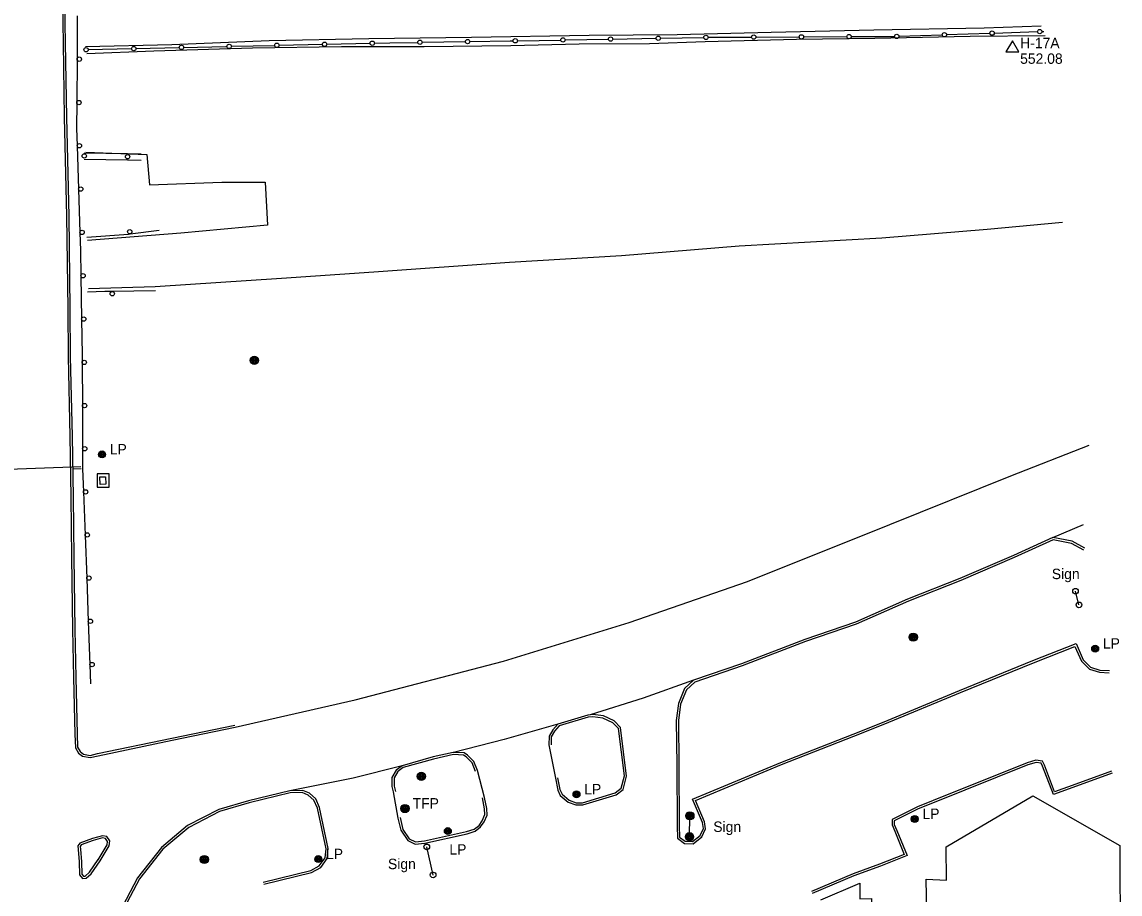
# Model space of a CAD drawing. Extents: x 2402803 to 2427059, y 6985292 to 6997652.
# Drawn here: x 2426548 to 2427055, y 6991142 to 6991544 of the extents above; entities that cross this region are included whole.
import ezdxf

# ---------------------------------------------------------------- set-up
doc = ezdxf.new("R2010")
doc.units = 0
for name, color, linetype in [('p_control ground ctrl', 7, 'Continuous'), ('p_dtm sidewalk', 7, 'Continuous'), ('p_road - paved curb', 7, 'Continuous'), ('p_road bridge end', 7, 'Continuous'), ('p_road conc barrier', 7, 'Continuous'), ('p_road guard fences', 7, 'Continuous'), ('p_road guard rails', 7, 'Continuous'), ('p_structure building', 7, 'Continuous'), ('p_structure general', 7, 'Continuous'), ('p_structure sidewalk', 7, 'Continuous'), ('p_structure sign', 7, 'Continuous'), ('p_structure slab', 7, 'Continuous'), ('p_utility manhole', 7, 'Continuous'), ('V7 LEVEL 31', 7, 'Continuous')]:
    doc.layers.add(name, color=color, linetype=linetype)

msp = doc.modelspace()

# ---------------------------------------------------------------- linework, layer by layer
at = {"layer": 'p_control ground ctrl'}
for p, q in [((2427005.25, 6991535.28), (2427002.25, 6991530.08)), ((2427008.25, 6991530.08), (2427005.25, 6991535.28)), ((2427005.25, 6991531.8), (2427005.25, 6991531.84)), ((2427002.25, 6991530.08), (2427008.25, 6991530.08))]:
    msp.add_line(p, q, dxfattribs=at)
at = {"layer": 'p_dtm sidewalk'}
msp.add_lwpolyline([(2426916.9, 6991138.89), (2426934.89, 6991146.51), (2426934.84, 6991139.28), (2426940.18, 6991139.42), (2426940.6, 6991129.38), (2426935.26, 6991129.19), (2426935.19, 6991127.67), (2426919.78, 6991132.5)], dxfattribs=at)
at = {"layer": 'p_road - paved curb'}
for points in [[(2426566.6, 6991580.37), (2426567.31, 6991534.06), (2426567.84, 6991500.02), (2426568.98, 6991454.31), (2426569.5, 6991411.55), (2426569.68, 6991389.4), (2426570.46, 6991352.79), (2426570.97, 6991324.68), (2426571.26, 6991296.91), (2426571.72, 6991263.57), (2426572.15, 6991241.38), (2426572.83, 6991215.32), (2426573.01, 6991209), (2426574.47, 6991206.56), (2426576.29, 6991205.17), (2426579.88, 6991204.48), (2426583.46, 6991205.37), (2426617.71, 6991212.47), (2426646.78, 6991218.51)], [(2426567.6, 6991580.39), (2426568.31, 6991534.08), (2426568.84, 6991500.04), (2426569.98, 6991454.33), (2426570.5, 6991411.56), (2426570.68, 6991389.41), (2426571.46, 6991352.81), (2426571.97, 6991324.69), (2426572.26, 6991296.92), (2426572.72, 6991263.59), (2426573.15, 6991241.4), (2426573.83, 6991215.35), (2426574, 6991209.29), (2426575.23, 6991207.24), (2426576.71, 6991206.11), (2426579.85, 6991205.5), (2426583.24, 6991206.35), (2426617.51, 6991213.45), (2426646.58, 6991219.49)], [(2426577.74, 6991532.56), (2426617.52, 6991533.57), (2426662.45, 6991535.42), (2426708.44, 6991536.29), (2426755.67, 6991536.93), (2426810.09, 6991537.76), (2426850.57, 6991538.13), (2426894.03, 6991539.26), (2426941.38, 6991540.29), (2426992.17, 6991541.15), (2427018.52, 6991542.07)], [(2427020.3, 6991537.5), (2426985.78, 6991537.17), (2426941.84, 6991536.32), (2426905.63, 6991535.84), (2426863.6, 6991534.7), (2426837.82, 6991533.85), (2426805.41, 6991533.7), (2426773.87, 6991532.91), (2426733.9, 6991532.48), (2426695.7, 6991532.41), (2426654.67, 6991531.77), (2426609.25, 6991530.45), (2426578.35, 6991529.16)], [(2426577.8, 6991483.77), (2426605.92, 6991482.82), (2426607.15, 6991468.72), (2426640.55, 6991469.94), (2426660.51, 6991470), (2426661.56, 6991450.15), (2426621.64, 6991446.53), (2426578.57, 6991443.15)], [(2426579, 6991420.97), (2426609.85, 6991421.93), (2426668.15, 6991425.68), (2426710.71, 6991428.7), (2426773.29, 6991433.03), (2426824.9, 6991436.1), (2426879.22, 6991440.63), (2426944.98, 6991444.33), (2426993.56, 6991448.33), (2427028.38, 6991451.56)], [(2426646.78, 6991218.51), (2426702.07, 6991231.21), (2426770.51, 6991248.95), (2426828.52, 6991266.8), (2426883.11, 6991285.77), (2426948.69, 6991312.02), (2427004.55, 6991334.44), (2427040.69, 6991348.63)], [(2427023.92, 6991306.03), (2427038.04, 6991312.12)], [(2427038.63, 6991301.15), (2427032.81, 6991304.28), (2427023.92, 6991306.03), (2427005.68, 6991297.8), (2426981.02, 6991287.2), (2426956.89, 6991277.57), (2426932.82, 6991266.94), (2426909.49, 6991258.93), (2426880.31, 6991247.83), (2426858.19, 6991240.23), (2426854.02, 6991236.37), (2426851.16, 6991229.48), (2426850.15, 6991221.62), (2426850.4, 6991201.02), (2426850.58, 6991172.94), (2426850.74, 6991167.34), (2426853.95, 6991164.89), (2426858.02, 6991164.73), (2426861.99, 6991167.95), (2426863.72, 6991171.61), (2426863.19, 6991174.8), (2426859.02, 6991184.76), (2426898.75, 6991201.34), (2426932.12, 6991214.44), (2426946.45, 6991220.08), (2426981.27, 6991234.6), (2427015.01, 6991248.29), (2427034.09, 6991255.81), (2427037.09, 6991249.03), (2427040.78, 6991245.34), (2427045.43, 6991243.91), (2427049.95, 6991243.66)], [(2427038.16, 6991300.27), (2427032.47, 6991303.33), (2427024.04, 6991304.99), (2427006.08, 6991296.88), (2426981.4, 6991286.28), (2426957.28, 6991276.65), (2426933.19, 6991266.01), (2426909.83, 6991257.99), (2426880.65, 6991246.89), (2426858.71, 6991239.35), (2426854.86, 6991235.78), (2426852.13, 6991229.22), (2426851.15, 6991221.56), (2426851.4, 6991201.03), (2426851.58, 6991172.96), (2426851.73, 6991167.85), (2426854.31, 6991165.88), (2426857.68, 6991165.74), (2426861.18, 6991168.58), (2426862.68, 6991171.75), (2426862.22, 6991174.52), (2426857.71, 6991185.3), (2426898.37, 6991202.27), (2426931.75, 6991215.37), (2426946.07, 6991221.01), (2426980.89, 6991235.52), (2427014.64, 6991249.22), (2427034.62, 6991257.09), (2427037.93, 6991249.61), (2427041.31, 6991246.22), (2427045.61, 6991244.9), (2427050.01, 6991244.66)], [(2426858.19, 6991240.23), (2426834.88, 6991231.88), (2426810.51, 6991224.21)], [(2426794.49, 6991195.05), (2426795.52, 6991189.47), (2426796.71, 6991186.98), (2426800.35, 6991183.97), (2426803.8, 6991182.63), (2426807.11, 6991182.66), (2426822.43, 6991187.3), (2426825.66, 6991189.73), (2426827.3, 6991195.98), (2426824.48, 6991218.36), (2426821.56, 6991221.43), (2426816.55, 6991223.7), (2426811.7, 6991224.37), (2426809.33, 6991224.06), (2426795.57, 6991219.97), (2426793.21, 6991217.27), (2426791.49, 6991214.39), (2426791.48, 6991210.34)], [(2426795.47, 6991195.23), (2426796.48, 6991189.78), (2426797.52, 6991187.61), (2426800.86, 6991184.84), (2426803.98, 6991183.63), (2426806.96, 6991183.66), (2426821.97, 6991188.21), (2426824.78, 6991190.32), (2426826.28, 6991196.05), (2426823.53, 6991217.91), (2426820.97, 6991220.6), (2426816.27, 6991222.73), (2426811.7, 6991223.36), (2426809.54, 6991223.08), (2426796.13, 6991219.09), (2426794.02, 6991216.68), (2426792.49, 6991214.11), (2426792.48, 6991210.34)], [(2426795.57, 6991219.97), (2426770.79, 6991212.79), (2426747.41, 6991206.89)], [(2426758.52, 6991198.53), (2426756.82, 6991202.65), (2426753.88, 6991205.69), (2426752.35, 6991206.64), (2426747.33, 6991206.89), (2426737.98, 6991204.79), (2426723.77, 6991200.76), (2426720.97, 6991198.74), (2426719.05, 6991195.36), (2426719.03, 6991191.2), (2426719.65, 6991188.63)], [(2426791.48, 6991210.34), (2426794.49, 6991195.05)], [(2426757.6, 6991198.15), (2426755.97, 6991202.09), (2426753.25, 6991204.91), (2426752.04, 6991205.65), (2426747.42, 6991205.88), (2426738.23, 6991203.82), (2426724.21, 6991199.85), (2426721.73, 6991198.06), (2426720.05, 6991195.09), (2426720.03, 6991191.32), (2426720.62, 6991188.86)], [(2427050.95, 6991198.31), (2427034.52, 6991192.25), (2427024.73, 6991188.73), (2427020.11, 6991200.95), (2427019.1, 6991202.88), (2427016.09, 6991203.27), (2427012, 6991202.11), (2426968.73, 6991184.73), (2426961.42, 6991181.77), (2426949.74, 6991175.97), (2426949.75, 6991173.49), (2426950.98, 6991170.5), (2426955.36, 6991159.83), (2426944.01, 6991155.37), (2426931.79, 6991150.92), (2426912.53, 6991142.7)], [(2427051.3, 6991197.37), (2427034.86, 6991191.31), (2427024.14, 6991187.46), (2427019.2, 6991200.54), (2427018.46, 6991201.96), (2427016.17, 6991202.25), (2427012.32, 6991201.16), (2426969.1, 6991183.8), (2426961.83, 6991180.86), (2426950.74, 6991175.35), (2426950.75, 6991173.69), (2426951.9, 6991170.88), (2426956.67, 6991159.27), (2426944.36, 6991154.43), (2426932.16, 6991149.99), (2426912.92, 6991141.78)], [(2426723.77, 6991200.76), (2426701.11, 6991194.96), (2426671.9, 6991189.21)], [(2426761.79, 6991186.15), (2426758.52, 6991198.53)], [(2426659.91, 6991146.05), (2426681.98, 6991151.49), (2426686.16, 6991153.8), (2426689.22, 6991157.9), (2426689.69, 6991162.48), (2426685.62, 6991181.44), (2426683.89, 6991185.45), (2426681, 6991188.04), (2426677.89, 6991189.34), (2426671.9, 6991189.21), (2426652.89, 6991184.53), (2426639.18, 6991180.59), (2426624.76, 6991173.13), (2426612.68, 6991162.95), (2426601.73, 6991149.07), (2426592.98, 6991132.61)], [(2426659.67, 6991147.02), (2426681.61, 6991152.43), (2426685.49, 6991154.57), (2426688.25, 6991158.28), (2426688.68, 6991162.42), (2426684.66, 6991181.13), (2426683.06, 6991184.85), (2426680.46, 6991187.18), (2426677.7, 6991188.34), (2426672.03, 6991188.21), (2426653.15, 6991183.56), (2426639.55, 6991179.66), (2426625.32, 6991172.29), (2426613.4, 6991162.25), (2426602.57, 6991148.52), (2426593.9, 6991132.22)], [(2426719.65, 6991188.63), (2426721.8, 6991176.55)], [(2426721.8, 6991176.55), (2426723.11, 6991170.94), (2426726.33, 6991166.3), (2426729.71, 6991164.6), (2426734.24, 6991165.09), (2426753.68, 6991169.38), (2426757.37, 6991170.55), (2426759.95, 6991172.54), (2426761.52, 6991174.8), (2426762.96, 6991177.99), (2426762.77, 6991180.97), (2426761.79, 6991186.15)], [(2426722.77, 6991176.78), (2426724.04, 6991171.35), (2426727.01, 6991167.08), (2426729.9, 6991165.63), (2426734.08, 6991166.08), (2426753.42, 6991170.35), (2426756.9, 6991171.45), (2426759.22, 6991173.24), (2426760.65, 6991175.3), (2426761.95, 6991178.17), (2426761.78, 6991180.84), (2426760.81, 6991185.96)], [(2426580.96, 6991167.16), (2426575.09, 6991165.08), (2426574.2, 6991163.8), (2426574.32, 6991162.14), (2426574.79, 6991156.41), (2426574.93, 6991150.41), (2426576.26, 6991148.74), (2426577.95, 6991148.89), (2426580.27, 6991150.91), (2426584.41, 6991156.85)], [(2426581.29, 6991166.22), (2426575.73, 6991164.24), (2426575.22, 6991163.52), (2426575.32, 6991162.22), (2426575.79, 6991156.46), (2426575.92, 6991150.77), (2426576.71, 6991149.78), (2426577.54, 6991149.86), (2426579.52, 6991151.58), (2426583.59, 6991157.42)], [(2426584.38, 6991156.85), (2426588.62, 6991163.84), (2426588.9, 6991166.09), (2426587.55, 6991168.04), (2426585.55, 6991168.43), (2426580.96, 6991167.16)], [(2426583.52, 6991157.37), (2426587.65, 6991164.18), (2426587.86, 6991165.83), (2426586.96, 6991167.14), (2426585.59, 6991167.4), (2426581.23, 6991166.2)]]:
    msp.add_lwpolyline(points, dxfattribs=at)
at = {"layer": 'p_road bridge end'}
msp.add_lwpolyline([(2426485.53, 6991336.63), (2426533.57, 6991337.32), (2426575.5, 6991338.77)], dxfattribs=at)
at = {"layer": 'p_road conc barrier'}
for p, q in [((2426577.05, 6991480.58), (2426597.05, 6991480.23)), ((2426577.1, 6991483.58), (2426597.1, 6991483.23)), ((2426597.05, 6991480.23), (2426603.36, 6991480.12)), ((2426597.1, 6991483.23), (2426603.41, 6991483.12))]:
    msp.add_line(p, q, dxfattribs=at)
for centre in [(2426577.08, 6991482.08), (2426597.07, 6991481.73)]:
    msp.add_circle(centre, 1, dxfattribs=at)
at = {"layer": 'p_road guard fences'}
for p, q in [((2426776.91, 6991535.23), (2426796.91, 6991535.59)), ((2426798.91, 6991535.63), (2426818.91, 6991535.99)), ((2426820.91, 6991536.03), (2426840.9, 6991536.39)), ((2426842.9, 6991536.43), (2426862.9, 6991536.79)), ((2426886.9, 6991536.95), (2426906.9, 6991537.05)), ((2426908.9, 6991537.06), (2426928.9, 6991537.16)), ((2426930.9, 6991537.17), (2426950.89, 6991537.27)), ((2426952.89, 6991537.33), (2426972.88, 6991538)), ((2426974.88, 6991538.06), (2426994.87, 6991538.73)), ((2426996.87, 6991538.8), (2427016.86, 6991539.46)), ((2427018.86, 6991539.53), (2427019.81, 6991539.56)), ((2426578.97, 6991531.16), (2426598.96, 6991531.62)), ((2426600.96, 6991531.66), (2426620.96, 6991532.12)), ((2426644.95, 6991532.68), (2426664.95, 6991533.12)), ((2426666.94, 6991533.17), (2426686.94, 6991533.61)), ((2426688.94, 6991533.66), (2426708.93, 6991534.11)), ((2426732.92, 6991534.54), (2426752.92, 6991534.85))]:
    msp.add_line(p, q, dxfattribs=at)
for points in [[(2426754.92, 6991534.88), (2426773.6, 6991535.17), (2426774.91, 6991535.19)], [(2426864.9, 6991536.83), (2426865.5, 6991536.84), (2426884.9, 6991536.94)], [(2426622.96, 6991532.17), (2426642.48, 6991532.62), (2426642.95, 6991532.63)], [(2426710.93, 6991534.15), (2426718.1, 6991534.31), (2426730.92, 6991534.51)]]:
    msp.add_lwpolyline(points, dxfattribs=at)
for centre in [(2427017.86, 6991539.49), (2426731.92, 6991534.52), (2426753.92, 6991534.87), (2426775.91, 6991535.21), (2426797.91, 6991535.61), (2426819.91, 6991536.01), (2426841.9, 6991536.41), (2426863.9, 6991536.81), (2426885.9, 6991536.94), (2426907.9, 6991537.05), (2426929.9, 6991537.16), (2426951.89, 6991537.27), (2426973.88, 6991538.03), (2426995.87, 6991538.76), (2426577.97, 6991531.13), (2426599.96, 6991531.64), (2426621.96, 6991532.15), (2426643.95, 6991532.65), (2426665.94, 6991533.14), (2426687.94, 6991533.64), (2426709.93, 6991534.13)]:
    msp.add_circle(centre, 1, dxfattribs=at)
at = {"layer": 'p_road guard rails'}
for p, q in [((2426573.78, 6991526.75), (2426573.67, 6991506.75)), ((2426573.86, 6991486.76), (2426574.5, 6991466.77)), ((2426574.5, 6991466.77), (2426575.13, 6991446.78)), ((2426598.22, 6991446.12), (2426611.68, 6991447.85)), ((2426575.57, 6991426.8), (2426575.87, 6991406.83)), ((2426610, 6991419.81), (2426590.01, 6991419.53)), ((2426576.13, 6991386.86), (2426576.22, 6991366.92)), ((2426576.22, 6991366.92), (2426576.3, 6991346.98)), ((2426576.74, 6991327.07), (2426577.48, 6991307.18)), ((2426578.22, 6991287.26), (2426578.97, 6991267.34)), ((2426578.97, 6991267.34), (2426579.71, 6991247.41)), ((2426579.71, 6991247.41), (2426580.04, 6991238.54))]:
    msp.add_line(p, q, dxfattribs=at)
for points in [[(2426573.84, 6991546.75), (2426573.88, 6991544.47), (2426573.78, 6991526.75)], [(2426573.67, 6991506.75), (2426573.6, 6991494.86), (2426573.86, 6991486.76)], [(2426575.13, 6991446.78), (2426575.4, 6991438.4), (2426575.57, 6991426.8)], [(2426578.28, 6991444.61), (2426597.49, 6991446.03), (2426598.22, 6991446.12)], [(2426590.01, 6991419.53), (2426586.61, 6991419.48), (2426578.6, 6991419.23)], [(2426575.87, 6991406.83), (2426576.12, 6991390.27), (2426576.13, 6991386.86)], [(2426576.3, 6991346.98), (2426576.34, 6991337.68), (2426576.74, 6991327.07)], [(2426577.48, 6991307.18), (2426577.49, 6991306.98), (2426578.22, 6991287.26)]]:
    msp.add_lwpolyline(points, dxfattribs=at)
for centre in [(2426574.78, 6991526.75), (2426574.67, 6991506.75), (2426574.86, 6991486.79), (2426575.5, 6991466.8), (2426576.13, 6991446.81), (2426598.09, 6991447.12), (2426576.57, 6991426.81), (2426590.02, 6991418.53), (2426576.87, 6991406.84), (2426577.13, 6991386.86), (2426577.22, 6991366.93), (2426577.3, 6991346.99), (2426577.74, 6991327.11), (2426578.48, 6991307.22), (2426579.22, 6991287.3), (2426579.97, 6991267.37), (2426580.71, 6991247.45)]:
    msp.add_circle(centre, 1, dxfattribs=at)
at = {"layer": 'p_structure building'}
msp.add_lwpolyline([(2426974.73, 6991163.37), (2427014.65, 6991186.78), (2427054.86, 6991163.99), (2427054.9, 6991119.06), (2427014.24, 6991094.54), (2426976.04, 6991118.17), (2426975.5, 6991130.63), (2426975.55, 6991132.85), (2426965.76, 6991132.74), (2426965.51, 6991148.48), (2426974.92, 6991147.99)], close=True, dxfattribs=at)
at = {"layer": 'p_structure general'}
msp.add_lwpolyline([(2426586.93, 6991334.09), (2426587.01, 6991330.63), (2426584.42, 6991330.57), (2426584.34, 6991334.03)], close=True, dxfattribs=at)
at = {"layer": 'p_structure sidewalk'}
msp.add_lwpolyline([(2426571.73, 6991337.7), (2426575.74, 6991337.9)], dxfattribs=at)
at = {"layer": 'p_structure sign'}
for p, q in [((2427035.95, 6991274.96), (2427034.36, 6991281.27)), ((2426856.28, 6991167.96), (2426856.47, 6991177.63)), ((2426738.03, 6991150.32), (2426735.11, 6991163.29))]:
    msp.add_line(p, q, dxfattribs=at)
for centre, radius in [((2427034.35, 6991281.28), 1.3), ((2427035.94, 6991274.97), 1.3), ((2426856.47, 6991177.63), 1.9), ((2426856.47, 6991177.63), 1.44), ((2426856.47, 6991177.63), 0.973), ((2426856.47, 6991177.63), 0.539), ((2426856.47, 6991177.63), 0.192), ((2426856.28, 6991167.96), 1.9), ((2426856.28, 6991167.96), 1.44), ((2426856.28, 6991167.96), 0.973), ((2426856.28, 6991167.96), 0.539), ((2426856.28, 6991167.96), 0.192), ((2426735.1, 6991163.3), 1.3), ((2426738.02, 6991150.33), 1.3)]:
    msp.add_circle(centre, radius, dxfattribs=at)
at = {"layer": 'p_structure slab'}
msp.add_lwpolyline([(2426583, 6991329.27), (2426588.62, 6991329.23), (2426588.66, 6991335.39), (2426583.04, 6991335.43)], close=True, dxfattribs=at)
at = {"layer": 'p_utility manhole'}
for centre, radius in [((2426655.58, 6991387.78), 1.9), ((2426655.58, 6991387.78), 1.44), ((2426655.58, 6991387.78), 0.973), ((2426655.58, 6991387.78), 0.539), ((2426655.58, 6991387.78), 0.192), ((2426585.29, 6991344.39), 1.6), ((2426585.29, 6991344.39), 1.3), ((2426585.29, 6991344.39), 1), ((2426585.29, 6991344.39), 0.539), ((2426585.29, 6991344.39), 0.192), ((2426959.5, 6991260.08), 1.9), ((2426959.5, 6991260.08), 1.44), ((2426959.5, 6991260.08), 0.973), ((2426959.5, 6991260.08), 0.539), ((2426959.5, 6991260.08), 0.192), ((2427043.43, 6991254.78), 1.6), ((2427043.43, 6991254.78), 1.3), ((2427043.43, 6991254.78), 1), ((2427043.43, 6991254.78), 0.539), ((2427043.43, 6991254.78), 0.192), ((2426732.6, 6991195.86), 1.9), ((2426732.6, 6991195.86), 1.44), ((2426732.6, 6991195.86), 0.973), ((2426732.6, 6991195.86), 0.539), ((2426732.6, 6991195.86), 0.192), ((2426804.18, 6991187.53), 1.6), ((2426804.18, 6991187.53), 1.3), ((2426804.18, 6991187.53), 1), ((2426804.18, 6991187.53), 0.539), ((2426804.18, 6991187.53), 0.192), ((2426725.02, 6991180.99), 1.9), ((2426725.02, 6991180.99), 1.44), ((2426725.02, 6991180.99), 0.973), ((2426725.02, 6991180.99), 0.539), ((2426725.02, 6991180.99), 0.192), ((2426960.2, 6991176.17), 1.6), ((2426960.2, 6991176.17), 1.3), ((2426960.2, 6991176.17), 1), ((2426960.2, 6991176.17), 0.539), ((2426960.2, 6991176.17), 0.192), ((2426744.83, 6991170.57), 1.6), ((2426744.83, 6991170.57), 1.3), ((2426744.83, 6991170.57), 1), ((2426744.83, 6991170.57), 0.539), ((2426744.83, 6991170.57), 0.192), ((2426632.52, 6991157.47), 1.9), ((2426632.52, 6991157.47), 1.44), ((2426632.52, 6991157.47), 0.973), ((2426632.52, 6991157.47), 0.539), ((2426632.52, 6991157.47), 0.192), ((2426685.05, 6991157.66), 1.6), ((2426685.05, 6991157.66), 1.3), ((2426685.05, 6991157.66), 1), ((2426685.05, 6991157.66), 0.539), ((2426685.05, 6991157.66), 0.192)]:
    msp.add_circle(centre, radius, dxfattribs=at)

# ---------------------------------------------------------------- texts
at = {"layer": 'p_control ground ctrl'}
msp.add_text('  H-17A', height=4.8, dxfattribs=at).set_placement((2427005.25, 6991531.8))
at = {"layer": 'p_structure sign'}
for p in [(2427023.42, 6991286.85), (2426867.26, 6991170.21), (2426717.2, 6991153.03)]:
    msp.add_text('Sign', height=4.8, dxfattribs=at).set_placement(p)
at = {"layer": 'p_utility manhole'}
for s, p in [('  LP', (2426585.29, 6991344.39)), ('  LP', (2427043.43, 6991254.78)), ('  LP', (2426804.18, 6991187.53)), ('  TFP', (2426725.02, 6991180.99)), ('  LP', (2426960.2, 6991176.17)), ('  LP', (2426685.05, 6991157.66)), ('  LP', (2426741.96, 6991159.75))]:
    msp.add_text(s, height=4.8, dxfattribs=at).set_placement(p)
at = {"layer": 'V7 LEVEL 31'}
msp.add_text('  552.08', height=4.8, dxfattribs=at).set_placement((2427005.25, 6991524.6))

doc.saveas('drawing.dxf')
